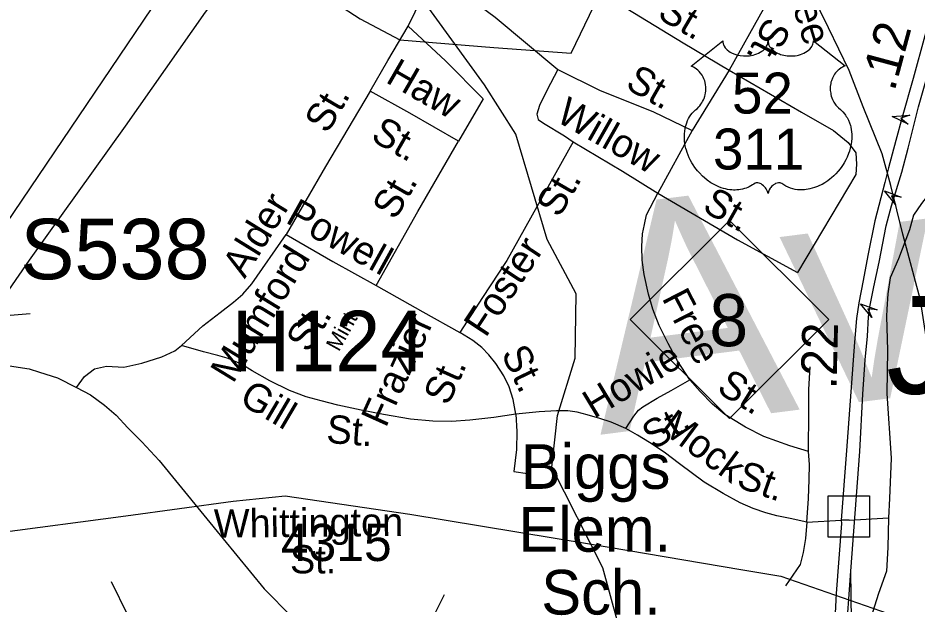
# Model space of a CAD drawing. Extents: x 1553981 to 1780076, y 812965 to 996873.
# Drawn here: x 1633663.3 to 1634040.5, y 847324.5 to 847570.6 of the extents above; entities that cross this region are included whole.
import ezdxf

# ---------------------------------------------------------------- set-up
doc = ezdxf.new("R2010")
doc.units = 0
for name, color, linetype in [('Exist Civil NCDOT Garage or Maintenance Office CELL', 7, 'Continuous'), ('Exist Cultural Educational Facility High Label', 7, 'Continuous'), ('Exist Cultural School High CELL', 7, 'Continuous'), ('Exist Geographical Pit Clay CELL', 7, 'Continuous'), ('Exist Hydrographic Creek Single Shore', 7, 'Continuous'), ('Exist Railroad Mainline', 7, 'Continuous'), ('Exist Road Non-System Structure Non-Sys Other CELL', 7, 'Continuous'), ('Exist Road Non-System Structure Non-Sys Other Number Label', 7, 'Continuous'), ('Exist Road Non-System Type 51 Label', 7, 'Continuous'), ('Exist Road Primary Interstate Structure Ovrhead Sign Number Label', 7, 'Continuous'), ('Exist Road Primary NC Shield Number Label', 7, 'Continuous'), ('Exist Road Primary US Divided Attributed', 7, 'Continuous'), ('Exist Road Primary US Ramp 1 Lane  Attributed', 7, 'Continuous'), ('Exist Road Primary US Structure Non-Sys NCDOT Number Label', 7, 'Continuous'), ('Exist Road Secondary Mileage Hundredths English Label', 7, 'Continuous'), ('Exist Road Secondary Type 51 Attributed', 7, 'Continuous'), ('Exist Road Secondary Type 51 Number Label', 7, 'Continuous'), ('Exist Utilities Electrical Transmission Line', 7, 'Continuous'), ('Map Preparation Border County Name Lower Right Label', 7, 'Continuous'), ('Map Preparation Border Division and District Label', 7, 'Continuous'), ('Map Preparation County Community Circle', 7, 'Continuous'), ('Map Preparation County Inset Title Block CELL', 7, 'Continuous')]:
    doc.layers.add(name, color=color, linetype=linetype)

msp = doc.modelspace()

# ---------------------------------------------------------------- linework, layer by layer
at = {"layer": 'Exist Cultural School High CELL'}
msp.add_lwpolyline([(1634036.79, 847525.99), (1634030.04, 847529.19), (1634037.49, 847529.79), (1634033.72, 847528.51)], close=True, dxfattribs=at)
at = {"layer": 'Exist Geographical Pit Clay CELL'}
msp.add_lwpolyline([(1633958.96, 847560.98), (1633958.99, 847560.43), (1633959.12, 847559.78), (1633959.23, 847559.44), (1633959.53, 847558.8), (1633960.03, 847558.04), (1633960.74, 847557.29), (1633961.53, 847556.64), (1633962.06, 847556.29), (1633962.97, 847555.81), (1633964, 847555.38), (1633965.14, 847555.05), (1633966.31, 847554.81), (1633967.59, 847554.67), (1633968.85, 847554.65), (1633970.22, 847554.75), (1633971.72, 847555.04), (1633972.42, 847555.22), (1633973.2, 847555.49), (1633973.92, 847555.78), (1633974.71, 847556.21), (1633975.35, 847556.62), (1633975.85, 847556.98), (1633976.55, 847557.65), (1633977.11, 847558.35), (1633977.35, 847558.74), (1633977.55, 847559.12), (1633977.83, 847559.92), (1633977.91, 847560.27), (1633977.97, 847561.01), (1633978.01, 847560.39), (1633978.08, 847560.01), (1633978.18, 847559.63), (1633978.33, 847559.23), (1633978.62, 847558.67), (1633978.93, 847558.19), (1633979.52, 847557.5), (1633979.89, 847557.15), (1633980.23, 847556.88), (1633981.13, 847556.26), (1633982.19, 847555.72), (1633982.7, 847555.49), (1633983.24, 847555.31), (1633983.91, 847555.1), (1633984.61, 847554.94), (1633985.3, 847554.82), (1633986.01, 847554.72), (1633986.73, 847554.66), (1633987.32, 847554.65), (1633988.04, 847554.65), (1633988.71, 847554.69), (1633989.39, 847554.77), (1633990.14, 847554.9), (1633990.75, 847555.03), (1633991.55, 847555.24), (1633992.27, 847555.5), (1633992.9, 847555.78), (1633993.73, 847556.21), (1633994.4, 847556.62), (1633994.88, 847557.02), (1633995.46, 847557.55), (1633996.01, 847558.19), (1633996.33, 847558.65), (1633996.56, 847559.13), (1633996.77, 847559.63), (1633996.9, 847560.16), (1633996.97, 847560.63), (1633996.98, 847561.02), (1634010.26, 847550.44), (1634009.95, 847550.32), (1634009.23, 847549.97), (1634008.65, 847549.63), (1634007.74, 847548.99), (1634007.35, 847548.63), (1634006.96, 847548.26), (1634006.6, 847547.87), (1634006.28, 847547.5), (1634005.89, 847546.97), (1634005.55, 847546.43), (1634005.21, 847545.85), (1634004.96, 847545.34), (1634004.56, 847544.27), (1634004.36, 847543.59), (1634004.23, 847543.02), (1634004.08, 847541.83), (1634004.04, 847541.27), (1634004.04, 847540.71), (1634004.07, 847540.12), (1634004.12, 847539.56), (1634004.23, 847538.97), (1634004.32, 847538.45), (1634004.48, 847537.82), (1634004.72, 847537.08), (1634005.01, 847536.36), (1634005.62, 847535.21), (1634006.4, 847534.03), (1634006.96, 847533.37), (1634007.51, 847532.81), (1634008.33, 847532.12), (1634008.77, 847531.72), (1634009.28, 847531.21), (1634010.11, 847530.25), (1634010.45, 847529.79), (1634010.79, 847529.28), (1634011.1, 847528.76), (1634011.42, 847528.19), (1634011.67, 847527.7), (1634012.13, 847526.56), (1634012.48, 847525.45), (1634012.63, 847524.87), (1634012.88, 847523.57), (1634012.97, 847522.92), (1634013.08, 847521.65), (1634013.08, 847520.11), (1634012.96, 847518.65), (1634012.69, 847516.95), (1634012.46, 847515.93), (1634012.11, 847514.74), (1634011.77, 847513.72), (1634011.17, 847512.2), (1634010.63, 847511.1), (1634009.93, 847509.82), (1634009.45, 847509.04), (1634008.89, 847508.21), (1634008.2, 847507.25), (1634007.38, 847506.23), (1634006.4, 847505.15), (1634005.61, 847504.36), (1634004.57, 847503.43), (1634003.94, 847502.92), (1634003.05, 847502.24), (1634001.83, 847501.42), (1634000.62, 847500.73), (1633999.59, 847500.2), (1633998.68, 847499.81), (1633997.5, 847499.36), (1633995.54, 847498.82), (1633994.83, 847498.67), (1633993.98, 847498.54), (1633993.19, 847498.46), (1633992.42, 847498.42), (1633991.38, 847498.42), (1633990.35, 847498.5), (1633989.38, 847498.64), (1633988.37, 847498.85), (1633987.31, 847499.16), (1633986.35, 847499.54), (1633985.38, 847500.02), (1633983.73, 847501.05), (1633983.26, 847501.31), (1633982.99, 847501.38), (1633982.36, 847501.41), (1633981.76, 847501.28), (1633981.15, 847501.04), (1633980.78, 847500.84), (1633980.29, 847500.52), (1633979.91, 847500.22), (1633979.46, 847499.79), (1633979.14, 847499.43), (1633978.9, 847499.15), (1633978.44, 847498.42), (1633978.28, 847498.07), (1633978.1, 847497.62), (1633977.95, 847496.97), (1633977.74, 847497.8), (1633977.5, 847498.35), (1633977.22, 847498.82), (1633976.92, 847499.23), (1633976.46, 847499.77), (1633976.04, 847500.17), (1633975.54, 847500.58), (1633975.01, 847500.9), (1633974.58, 847501.12), (1633974.19, 847501.27), (1633973.71, 847501.38), (1633973.32, 847501.42), (1633973, 847501.41), (1633972.55, 847501.31), (1633971.95, 847500.87), (1633971.38, 847500.48), (1633970.76, 847500.1), (1633970.03, 847499.7), (1633969.48, 847499.45), (1633968.84, 847499.2), (1633968.09, 847498.95), (1633967.27, 847498.74), (1633966.43, 847498.57), (1633965.7, 847498.46), (1633964.9, 847498.39), (1633964.19, 847498.36), (1633963.44, 847498.37), (1633962.75, 847498.42), (1633961.94, 847498.5), (1633960.93, 847498.64), (1633960.1, 847498.83), (1633959.22, 847499.07), (1633958.32, 847499.35), (1633957.36, 847499.72), (1633956.15, 847500.25), (1633955.31, 847500.68), (1633953.98, 847501.44), (1633952.43, 847502.51), (1633951.26, 847503.46), (1633950.4, 847504.24), (1633949.13, 847505.53), (1633948.39, 847506.37), (1633947.23, 847507.88), (1633946.48, 847508.97), (1633946, 847509.77), (1633945.29, 847511.06), (1633944.9, 847511.86), (1633944.4, 847513.04), (1633944.01, 847514.12), (1633943.68, 847515.14), (1633943.5, 847515.79), (1633943.25, 847516.93), (1633943.1, 847517.74), (1633942.95, 847518.84), (1633942.86, 847520.01), (1633942.85, 847521.09), (1633942.88, 847521.98), (1633942.98, 847523.03), (1633943.15, 847524.13), (1633943.37, 847525.08), (1633943.56, 847525.77), (1633943.84, 847526.6), (1633944.21, 847527.52), (1633944.65, 847528.4), (1633945.07, 847529.13), (1633945.6, 847529.91), (1633946.12, 847530.58), (1633946.8, 847531.32), (1633947.5, 847531.99), (1633948.15, 847532.52), (1633948.92, 847533.27), (1633949.32, 847533.73), (1633949.8, 847534.36), (1633950.18, 847534.95), (1633950.49, 847535.48), (1633950.9, 847536.25), (1633951.14, 847536.83), (1633951.44, 847537.73), (1633951.6, 847538.36), (1633951.75, 847539.17), (1633951.86, 847539.93), (1633951.9, 847540.88), (1633951.87, 847541.66), (1633951.77, 847542.58), (1633951.6, 847543.46), (1633951.39, 847544.23), (1633951.06, 847545.11), (1633950.76, 847545.75), (1633950.25, 847546.62), (1633949.68, 847547.43), (1633949.1, 847548.09), (1633948.51, 847548.68), (1633947.94, 847549.12), (1633947.41, 847549.5), (1633946.73, 847549.91), (1633946.08, 847550.23), (1633945.67, 847550.4)], close=True, dxfattribs=at)
at = {"layer": 'Exist Hydrographic Creek Single Shore'}
for points in [[(1633453.91, 847425.16), (1633500.42, 847416.57), (1633577.33, 847410.87), (1633610.8, 847435.1), (1633648.04, 847469.09), (1633722.84, 847579.82), (1633733.36, 847597.48)], [(1633959.21, 847220.5), (1633943.72, 847233.12), (1633931.47, 847247.74), (1633915.46, 847304.27), (1633914.59, 847317.83), (1633908.59, 847339.7), (1633887.22, 847381.99), (1633889.59, 847403.68), (1633897.08, 847427.75), (1633897.47, 847454.82), (1633885.22, 847477.64), (1633872.21, 847521.81), (1633858.97, 847542.59), (1633831.56, 847580.5), (1633798.8, 847599.03), (1633762.49, 847587.62), (1633733.36, 847597.48)]]:
    msp.add_lwpolyline(points, dxfattribs=at)
at = {"layer": 'Exist Railroad Mainline'}
msp.add_lwpolyline([(1634069.59, 847336.99), (1634065.04, 847351.37), (1634060.64, 847368.98), (1634051.46, 847399.41), (1634045.72, 847427.64), (1634041.88, 847452.15), (1634034.57, 847479.87), (1634029.42, 847500.24), (1634025.86, 847513.54), (1634017.81, 847533.26), (1634011.98, 847548.57), (1634003.31, 847566.4), (1633992.69, 847588.28), (1633986.83, 847606.17), (1633984.64, 847618.48), (1633983.29, 847629.76), (1633984.15, 847641.13), (1633985.54, 847652.88), (1633986.19, 847663.47), (1633989.36, 847672.75), (1633996.01, 847690.35), (1634006.19, 847708.12), (1634011.33, 847719.83)], dxfattribs=at)
at = {"layer": 'Exist Road Non-System Structure Non-Sys Other CELL'}
msp.add_lwpolyline([(1634003.12, 847370.03), (1634020.49, 847370.03), (1634020.49, 847352.65), (1634003.12, 847352.65)], close=True, dxfattribs=at)
at = {"layer": 'Exist Road Primary US Divided Attributed'}
for points in [[(1634049.68, 847585.33), (1634046.57, 847573.46), (1634043.72, 847563.12), (1634038.88, 847545.12), (1634034.23, 847529), (1634031.55, 847519.09), (1634028.43, 847507.67), (1634026.96, 847501.49)], [(1634029.71, 847491.66), (1634034.09, 847505.93), (1634036.7, 847515.94), (1634041.1, 847533.32), (1634043.66, 847542.08), (1634049.27, 847562.54), (1634053.59, 847578.48)], [(1634026.96, 847501.49), (1634022.77, 847485.46), (1634019.87, 847470.83), (1634017.81, 847460.39), (1634016.03, 847451.02), (1634015.09, 847444.47), (1634014.25, 847434.54), (1634010.87, 847388.97), (1634008.69, 847359.68)], [(1634012.68, 847338.3), (1634016.5, 847388.61), (1634017.78, 847412.61), (1634018.75, 847427.02), (1634019.68, 847437.02), (1634020.09, 847445.12), (1634020.6, 847449.31), (1634022.31, 847457.77), (1634024.55, 847468.02), (1634027.56, 847483.28), (1634029.71, 847491.66)], [(1634008.69, 847359.68), (1634008.73, 847358.29), (1634006.57, 847328.94), (1634005.39, 847306.9)], [(1634032.18, 847144.15), (1634028.67, 847149.34), (1634024.98, 847156.29), (1634021.55, 847162.48), (1634017.62, 847171.02), (1634013.85, 847180.32), (1634011.76, 847186.09), (1634009.33, 847195.3), (1634008.31, 847202.49), (1634007.07, 847210.04), (1634006.15, 847219.25), (1634005.73, 847225.78), (1634005.9, 847232.64), (1634005.95, 847244.55), (1634008.99, 847285.72), (1634010.58, 847309.16), (1634012.68, 847338.3)]]:
    msp.add_lwpolyline(points, dxfattribs=at)
at = {"layer": 'Exist Road Primary US Ramp 1 Lane  Attributed'}
msp.add_lwpolyline([(1634034.3, 847165), (1634030.68, 847171.36), (1634025.07, 847181.24), (1634019.12, 847192.04), (1634015.69, 847199.4), (1634011.34, 847211.71), (1634008.75, 847231.55), (1634013.01, 847317.45), (1634012.68, 847338.3)], dxfattribs=at)
at = {"layer": 'Exist Road Secondary Type 51 Attributed'}
msp.add_lwpolyline([(1633631.09, 847424.01), (1633651.63, 847425.39), (1633659.79, 847424.6), (1633667.94, 847423.23), (1633672.27, 847421.85), (1633679.83, 847419.49), (1633687.79, 847415.46), (1633693.69, 847412.42), (1633699.59, 847408.09), (1633704.5, 847403.77), (1633709.42, 847398.46), (1633715.31, 847392.66), (1633722.58, 847384.8), (1633749.41, 847351.88), (1633766.61, 847330.95), (1633778.21, 847319.15)], dxfattribs=at)
at = {"layer": 'Exist Utilities Electrical Transmission Line'}
for points in [[(1633637.57, 847424.84), (1633668.1, 847468.95), (1633708.32, 847525.19), (1633741.9, 847573.01), (1633755.11, 847590.35), (1633761.98, 847599.51), (1633787.01, 847583.2), (1633806.83, 847570.19), (1633823.44, 847561.47), (1633862.89, 847558.19), (1633895.33, 847555.78), (1633916.64, 847600), (1633942.25, 847650.18), (1633952.27, 847671.56), (1634023.32, 847677.4), (1634090.81, 847681.25), (1634113.84, 847683.46), (1634161.85, 847687.34), (1634229.39, 847692.47), (1634261.14, 847695.55), (1634281.91, 847697.06), (1634321.69, 847720.79)], [(1633508.03, 847332.85), (1633537.84, 847338.72), (1633586.39, 847345.09), (1633653.46, 847354.23), (1633708.52, 847361.52), (1633753.57, 847367.71), (1633775.32, 847369.92), (1633827.69, 847362.25), (1633902.98, 847349.79), (1633966.55, 847338.97), (1633983.25, 847336.25), (1634034.74, 847318.32)]]:
    msp.add_lwpolyline(points, dxfattribs=at)
at = {"layer": 'Map Preparation Border County Name Lower Right Label'}
for p, q in [((1633826.93, 847567.15), (1633838.88, 847591.66)), ((1633976.05, 847574.37), (1633961.61, 847548.63)), ((1633961.61, 847548.63), (1633946.13, 847523.34)), ((1633946.13, 847523.34), (1633931.78, 847497.1)), ((1633668.39, 847446.31), (1633654.89, 847445.28)), ((1633871.28, 847380.23), (1633877.02, 847379.38)), ((1634012, 847359.72), (1634008.69, 847359.68)), ((1633842.02, 847328.42), (1633821.91, 847288.23))]:
    msp.add_line(p, q, dxfattribs=at)
for points in [[(1633838.88, 847591.66), (1633853.78, 847578.13), (1633863.44, 847570.95), (1633889.82, 847549.02)], [(1633886.52, 847592.23), (1633915.52, 847576.53), (1633942.29, 847560.23), (1633961.61, 847548.63)], [(1633811.02, 847539.88), (1633818.46, 847552.77), (1633826.93, 847567.15)], [(1633826.93, 847567.15), (1633842.69, 847552.65), (1633858.43, 847536.67), (1633848.16, 847518.82)], [(1633889.82, 847549.02), (1633885.13, 847540.18), (1633882.1, 847533.83), (1633880.99, 847530.24), (1633881.54, 847528.03), (1633883.75, 847526.38), (1633892.58, 847521.13), (1633896.17, 847518.64)], [(1633889.82, 847549.02), (1633907.49, 847540.18), (1633929.57, 847531.35), (1633946.13, 847523.34)], [(1633961.61, 847548.63), (1633991.94, 847531.07), (1634005.47, 847523.34), (1634011.54, 847518.37), (1634014.85, 847513.95), (1634015.13, 847509.25), (1634014.85, 847504.83), (1633990.29, 847463.69)], [(1633811.02, 847539.88), (1633792.29, 847508.17), (1633775.85, 847479.67)], [(1633848.16, 847518.82), (1633827.61, 847530.64), (1633811.02, 847539.88)], [(1633813.51, 847458.34), (1633830.98, 847489.33), (1633848.16, 847518.82)], [(1633896.17, 847518.64), (1633868.4, 847468.76), (1633858.16, 847453.18), (1633848.71, 847438.57)], [(1633896.17, 847518.64), (1633916.87, 847506.22), (1633931.78, 847497.1)], [(1634053.91, 847507.68), (1634046.71, 847498.27), (1634042.29, 847492.73), (1634038.97, 847487.75), (1634037.31, 847481.66), (1634032.68, 847469.49), (1634029.15, 847461.56), (1634028.19, 847454.73), (1634027.78, 847448.27), (1634027.61, 847445.27)], [(1633945.1, 847418.6), (1633939.96, 847426.68), (1633936.08, 847433.99), (1633932.21, 847441.55), (1633929.55, 847448.33), (1633927.8, 847454.57), (1633926.04, 847462.88), (1633925.11, 847468.9), (1633924.95, 847474.66), (1633925.29, 847479.91), (1633926.09, 847483.89), (1633926.92, 847487.88), (1633931.78, 847497.1)], [(1633931.78, 847497.1), (1633965.17, 847477.49), (1633990.29, 847463.69)], [(1633731.82, 847433.15), (1633740.86, 847441.31), (1633748.13, 847446.91), (1633753.74, 847451.23), (1633757.57, 847454.67), (1633761.4, 847459), (1633775.85, 847479.67)], [(1633775.85, 847479.67), (1633795.43, 847468.39), (1633813.51, 847458.34)], [(1633813.51, 847458.34), (1633833.1, 847447.24), (1633848.71, 847438.57)], [(1634027.61, 847445.27), (1634028.03, 847431.17), (1634027.73, 847412.92), (1634029.55, 847385.81), (1634028.96, 847368.89), (1634028.48, 847360.69)], [(1633872.17, 847404.22), (1633871, 847410.47), (1633869.33, 847415.76), (1633867.14, 847420.28), (1633863.75, 847425.58), (1633860.8, 847429.14), (1633857.93, 847432.27), (1633854.14, 847435.23), (1633848.71, 847438.57)], [(1633687.79, 847415.46), (1633691.23, 847420.08), (1633695.36, 847423.23), (1633700.37, 847424.41), (1633707.74, 847424.01), (1633715.31, 847425.68), (1633723.66, 847428.34), (1633729.07, 847430.79), (1633731.82, 847433.15)], [(1633747.1, 847428.87), (1633741.11, 847430.45), (1633731.82, 847433.15)], [(1633872.17, 847404.22), (1633862.89, 847402.86), (1633852.89, 847401.76), (1633845.22, 847401.24), (1633837.37, 847401.25), (1633827.9, 847402.14), (1633816.69, 847404.05), (1633807.22, 847405.94), (1633797.53, 847408.01), (1633790.54, 847409.83), (1633784.15, 847411.54), (1633777.15, 847414.16), (1633768.93, 847418.27), (1633761.48, 847422.4), (1633757.53, 847424.96), (1633753.57, 847426.77), (1633751.08, 847427.79), (1633747.1, 847428.87)], [(1633994.87, 847388.6), (1633995.11, 847405.32), (1633995.02, 847414.58), (1633995.66, 847424.07)], [(1633918.3, 847398.26), (1633921.63, 847403.47), (1633923.66, 847405.93), (1633925.44, 847407.39), (1633931.49, 847411.04), (1633937.28, 847414.23), (1633945.1, 847418.6)], [(1633994.87, 847388.6), (1633987.16, 847390.95), (1633976.21, 847394.88), (1633968.53, 847398.74), (1633959.86, 847404.11), (1633954.67, 847408.45), (1633949.53, 847413.78), (1633945.1, 847418.6)], [(1633872.17, 847404.22), (1633872.55, 847396.96), (1633872.42, 847389.46), (1633871.28, 847380.23)], [(1633918.3, 847398.26), (1633912.1, 847400.86), (1633907.35, 847402.43), (1633902.13, 847404.01), (1633897.9, 847405.07), (1633893.91, 847405.63), (1633889.18, 847405.7), (1633881.92, 847405.3), (1633872.17, 847404.22)], [(1633994.16, 847358.84), (1633987.19, 847360.46), (1633981.71, 847361.55), (1633976.99, 847362.87), (1633971.77, 847364.7), (1633966.29, 847367.01), (1633959.11, 847370.89), (1633951.18, 847375.75), (1633940.81, 847383.42), (1633934.38, 847388.27), (1633928.21, 847392.35), (1633923.24, 847395.43), (1633918.3, 847398.26)], [(1633994.16, 847358.84), (1633994.99, 847368.86), (1633995.18, 847376.83), (1633995.28, 847383.08), (1633994.87, 847388.6)], [(1633994.16, 847358.84), (1634008.69, 847359.68)], [(1634012, 847359.72), (1634028.48, 847360.69)], [(1634028.48, 847360.69), (1634028.24, 847348.32), (1634027.59, 847338.35), (1634024.31, 847329.01), (1634020.88, 847318.37), (1634020.13, 847311.42), (1634019.71, 847305.56), (1634019.88, 847300.88), (1634020.88, 847295.6), (1634023.06, 847288.07), (1634031.24, 847267.04), (1634032.03, 847258.15), (1634032.29, 847251.6), (1634033.04, 847239.27), (1634032.54, 847226.93), (1634033.04, 847208.8), (1634033.54, 847194.2), (1634033.8, 847182.12), (1634034.3, 847165)], [(1633994.16, 847358.84), (1633993.73, 847352.07), (1633992.7, 847346.12), (1633991.38, 847341.14), (1633985.3, 847332.19)], [(1633702.41, 847334.05), (1633709.2, 847319.93), (1633716.48, 847306.58)]]:
    msp.add_lwpolyline(points, dxfattribs=at)
at = {"layer": 'Map Preparation Border Division and District Label'}
msp.add_lwpolyline([(1633920.18, 847444), (1633961.8, 847485.62), (1634003.42, 847444), (1633961.8, 847402.38)], close=True, dxfattribs=at)
at = {"layer": 'Map Preparation County Community Circle'}
msp.add_lwpolyline([(1634031.45, 847492.24), (1634026.78, 847498.07), (1634033.74, 847495.35), (1634029.79, 847495.86)], close=True, dxfattribs=at)
at = {"layer": 'Map Preparation County Inset Title Block CELL'}
msp.add_lwpolyline([(1634021.56, 847444.83), (1634016.76, 847450.55), (1634023.78, 847447.99), (1634019.82, 847448.41)], close=True, dxfattribs=at)

# ---------------------------------------------------------------- texts
at = {"layer": 'Exist Civil NCDOT Garage or Maintenance Office CELL'}
for s, p in [('52', (1633962.82, 847530.47)), ('311', (1633954.84, 847506.98))]:
    msp.add_text(s, height=17.188, dxfattribs=at).set_placement(p)
at = {"layer": 'Exist Cultural Educational Facility High Label'}
for s, p in [('Biggs', (1633874.26, 847372.9)), ('Elem.', (1633873.24, 847346.51)), ('Sch.', (1633882.81, 847320.12))]:
    msp.add_text(s, height=18.75, dxfattribs=at).set_placement(p)
at = {"layer": 'Exist Road Non-System Structure Non-Sys Other Number Label'}
msp.add_text('J136', height=41.01, dxfattribs=at).set_placement((1634027.48, 847412.81))
at = {"layer": 'Exist Road Non-System Type 51 Label'}
for s, height, rotation, p in [('Free', 11.875, 286.9422, (1633983.87, 847589.56)), ('St.', 11.875, 329.2733, (1633931.01, 847570.89)), ('St.', 11.875, 242.2073, (1633977.51, 847571.62)), ('Haw', 11.875, 330.0813, (1633817.05, 847543.82)), ('St.', 11.875, 330.2911, (1633917.61, 847541.36)), ('St.', 11.875, 59.4343, (1633793.08, 847521.6)), ('Willow', 11.875, 330.4395, (1633888.41, 847527.56)), ('St.', 11.875, 330.0813, (1633810.75, 847519.55)), ('St.', 11.875, 59.7744, (1633821.53, 847485.33)), ('St.', 11.875, 60.0304, (1633890.36, 847486.32)), ('St.', 11.875, 330.6273, (1633949.87, 847489.83)), ('Alder', 11.875, 58.2488, (1633758.4, 847460.84)), ('Ave.', 95, 7.1831, (1633907.41, 847395.59)), ('Powell', 11.875, 330.9388, (1633775.07, 847484.91)), ('Foster', 11.875, 56.6595, (1633859.51, 847436.01)), ('Mumford', 11.875, 58.4845, (1633753.48, 847416.75)), ('Free', 11.875, 297.1379, (1633933.23, 847453.03)), ('St.', 11.875, 58.4845, (1633785.18, 847429.58)), ('Mint', 6.562, 61.0224, (1633797.89, 847430.22)), ('Frazier', 11.875, 65.7549, (1633817.59, 847398.18)), ('St.', 11.875, 295.7824, (1633865.8, 847429.75)), ('Howie', 11.875, 31.1211, (1633904.93, 847402.2)), ('St.', 11.875, 65.7549, (1633843.77, 847407.4)), ('St.', 11.875, 328.1855, (1633955.91, 847413.81)), ('Gill', 11.875, 329.53, (1633755.53, 847409.02)), ('St.', 11.875, 31.1211, (1633929.76, 847388.94)), ('Mock', 11.875, 323.5433, (1633932.19, 847397.43)), ('St.', 11.875, 355.422, (1633792.41, 847392.26)), ('St.', 11.875, 340.647, (1633964.2, 847373.88)), ('Whittington', 11.875, 0.5085, (1633745.5, 847352.4)), ('St.', 11.875, 359.8686, (1633777.4, 847337.42))]:
    msp.add_text(s, height=height, rotation=rotation, dxfattribs=at).set_placement(p)
at = {"layer": 'Exist Road Primary Interstate Structure Ovrhead Sign Number Label'}
msp.add_text('S538', height=25.426, dxfattribs=at).set_placement((1633664.28, 847460.88))
at = {"layer": 'Exist Road Primary NC Shield Number Label'}
msp.add_text('8', height=21.88, dxfattribs=at).set_placement((1633953.32, 847432.79))
at = {"layer": 'Exist Road Primary US Structure Non-Sys NCDOT Number Label'}
msp.add_text('H124', height=25.426, dxfattribs=at).set_placement((1633752.97, 847422.22))
at = {"layer": 'Exist Road Secondary Mileage Hundredths English Label'}
for s, rotation, p in [('.12', 74.9435, (1634030.97, 847539.43)), ('.22', 88.641, (1634006.67, 847414.61))]:
    msp.add_text(s, height=15, rotation=rotation, dxfattribs=at).set_placement(p)
at = {"layer": 'Exist Road Secondary Type 51 Number Label'}
msp.add_text('4315', height=15.625, dxfattribs=at).set_placement((1633773.57, 847342.6))

doc.saveas('drawing.dxf')
